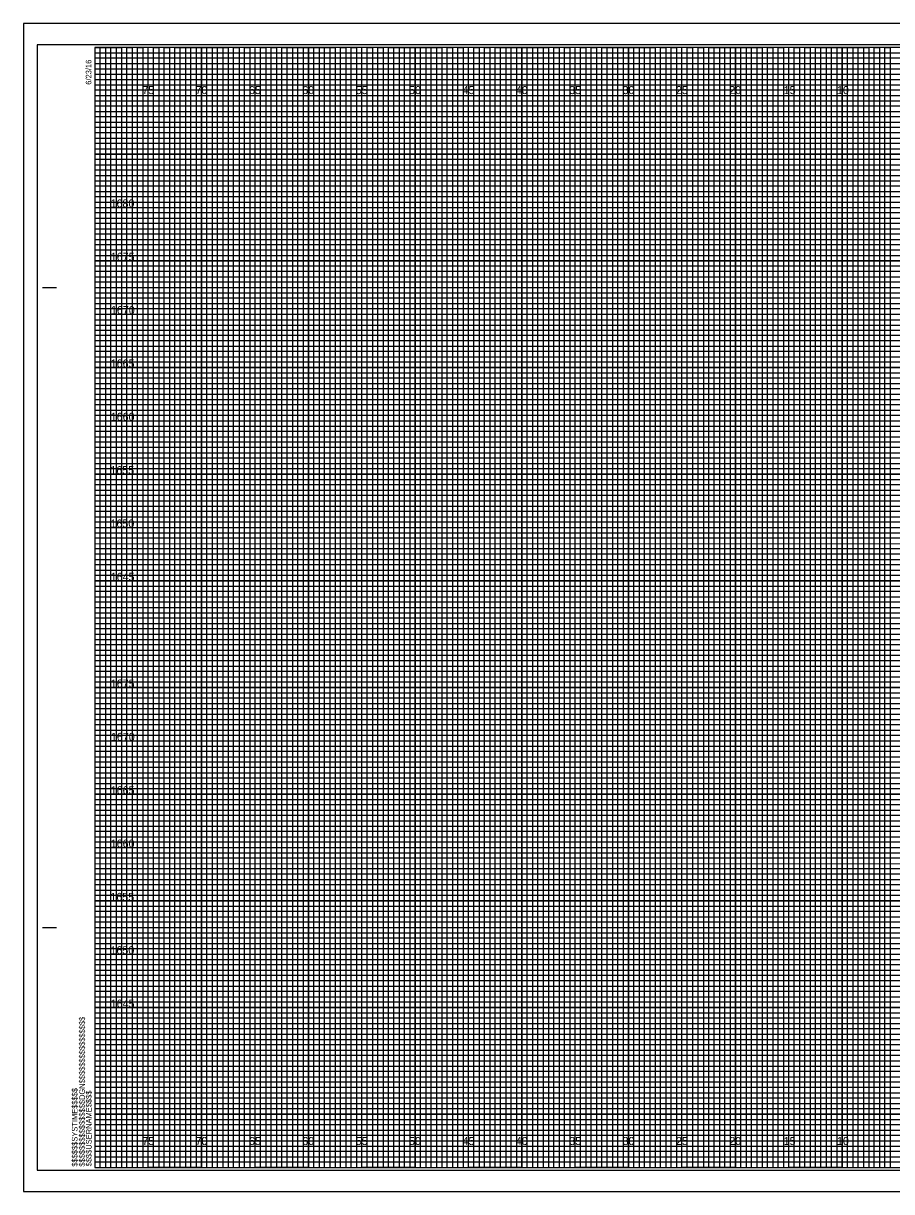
# Model space of a CAD drawing. Extents: x -7 to 162, y -2 to 217.
# Drawn here: x -6.7 to 74.6, y -2.3 to 107.3 of the extents above; entities that cross this region are included whole.
import ezdxf

# ---------------------------------------------------------------- set-up
doc = ezdxf.new("R2010")
doc.units = 0
for name, color, linetype in [('Prop XS Gore Control Minimum', 7, 'Continuous'), ('Raster_Level_0', 7, 'Continuous'), ('Scratch_Level_3', 7, 'Continuous'), ('Sheet Cross Section CELL', 7, 'Continuous'), ('Sheet Cross Section Grid Middle CELL', 7, 'Continuous'), ('Sheet Cross Section Grid Minor 1 CELL', 7, 'Continuous'), ('Sheet Cross Section Grid Minor 2 CELL', 7, 'Continuous'), ('Sheet Cutting Line CELL', 7, 'Continuous'), ('Sheet DOT Grid CELL', 7, 'Continuous'), ('Sheet Plot Border Inside CELL', 7, 'Continuous'), ('Sheet Plot Border Outside CELL', 7, 'Continuous')]:
    doc.layers.add(name, color=color, linetype=linetype)

msp = doc.modelspace()

# ---------------------------------------------------------------- linework, layer by layer
at = {"layer": 'Prop XS Gore Control Minimum'}
for p, q in [((5, 105), (0, 105)), ((5, 0), (5, 105)), ((15, 105), (10, 105)), ((10, 105), (10, 0)), ((15, 0), (15, 105)), ((25, 105), (20, 105)), ((20, 105), (20, 0)), ((25, 0), (25, 105)), ((35, 105), (30, 105)), ((30, 105), (30, 0)), ((35, 0), (35, 105)), ((45, 105), (40, 105)), ((40, 105), (40, 0)), ((45, 0), (45, 105)), ((55, 105), (50, 105)), ((50, 105), (50, 0)), ((55, 0), (55, 105)), ((65, 105), (60, 105)), ((60, 105), (60, 0)), ((65, 0), (65, 105)), ((75, 105), (70, 105)), ((70, 105), (70, 0)), ((10, 0), (5, 0)), ((20, 0), (15, 0)), ((30, 0), (25, 0)), ((40, 0), (35, 0)), ((50, 0), (45, 0)), ((60, 0), (55, 0)), ((70, 0), (65, 0))]:
    msp.add_line(p, q, dxfattribs=at)
for points in [[(0, 100), (160, 100), (160, 95), (0, 95)], [(0, 90), (160, 90), (160, 85), (0, 85)], [(0, 80), (160, 80), (160, 75), (0, 75)], [(0, 70), (160, 70), (160, 65), (0, 65)], [(0, 60), (160, 60), (160, 55), (0, 55)], [(0, 50), (160, 50), (160, 45), (0, 45)], [(0, 40), (160, 40), (160, 35), (0, 35)], [(0, 30), (160, 30), (160, 25), (0, 25)], [(0, 20), (160, 20), (160, 15), (0, 15)], [(0, 10), (160, 10), (160, 5), (0, 5)]]:
    msp.add_lwpolyline(points, dxfattribs=at)
at = {"layer": 'Sheet Cross Section CELL'}
for p, q in [((-4.9, 82.5), (-3.65, 82.5)), ((-4.85, 82.5), (-3.6, 82.5)), ((-4.9, 22.5), (-3.65, 22.5)), ((-4.85, 22.5), (-3.6, 22.5)), ((0, 0), (0, 0)), ((0, 0), (0, 0)), ((0, 0), (0, 0)), ((0, 0), (0, 0)), ((0, 0), (0, 0)), ((0, 0), (0, 0)), ((0, 0), (0, 0))]:
    msp.add_line(p, q, dxfattribs=at)
msp.add_lwpolyline([(160, 105), (0, 105), (0, 0), (160, 0)], close=True, dxfattribs=at)
at = {"layer": 'Sheet Cross Section Grid Middle CELL'}
for points in [[(0, 105), (2.5, 105), (2.5, 0), (7.5, 0), (7.5, 105), (12.5, 105), (12.5, 0), (17.5, 0), (17.5, 105), (22.5, 105), (22.5, 0), (27.5, 0), (27.5, 105), (32.5, 105), (32.5, 0), (37.5, 0), (37.5, 105), (42.5, 105), (42.5, 0), (47.5, 0), (47.5, 105), (52.5, 105), (52.5, 0), (57.5, 0), (57.5, 105), (62.5, 105), (62.5, 0), (67.5, 0), (67.5, 105), (72.5, 105), (72.5, 0), (77.5, 0)], [(0, 102.5), (137.5, 102.5)], [(0, 92.5), (160, 92.5), (160, 97.5), (0, 97.5)], [(0, 82.5), (160, 82.5), (160, 87.5), (0, 87.5)], [(0, 72.5), (160, 72.5), (160, 77.5), (0, 77.5)], [(0, 62.5), (160, 62.5), (160, 67.5), (0, 67.5)], [(0, 52.5), (160, 52.5), (160, 57.5), (0, 57.5)], [(0, 42.5), (160, 42.5), (160, 47.5), (0, 47.5)], [(0, 32.5), (160, 32.5), (160, 37.5), (0, 37.5)], [(0, 22.5), (160, 22.5), (160, 27.5), (0, 27.5)], [(0, 12.5), (160, 12.5), (160, 17.5), (0, 17.5)], [(0, 2.5), (160, 2.5), (160, 7.5), (0, 7.5)]]:
    msp.add_lwpolyline(points, dxfattribs=at)
at = {"layer": 'Sheet Cross Section Grid Minor 1 CELL'}
for p, q in [((0, 104.5), (130, 104.5)), ((130, 103.99), (0, 103.99)), ((0, 103.99), (0, 103.5)), ((0, 103.5), (130, 103.5)), ((130, 102.95), (0, 102.95)), ((0, 102.95), (0, 102)), ((0, 102), (160, 102))]:
    msp.add_line(p, q, dxfattribs=at)
for points in [[(0, 101.5), (135, 101.5), (160, 101.5), (160, 101), (0, 101)], [(0, 100.5), (160, 100.5), (160, 99.5), (0, 99.5)], [(0, 99), (160, 99), (160, 98.5), (0, 98.49)], [(0, 98), (160, 98), (160, 97), (0, 97)], [(0, 96.5), (160, 96.5), (160, 96), (0, 96)], [(0, 95.5), (160, 95.5), (160, 94.5), (0, 94.5)], [(0, 94), (160, 94), (160, 93.5), (0, 93.5)], [(0, 93), (160, 93), (160, 92), (0, 92)], [(0, 91.5), (160, 91.5), (160, 91), (0, 91)], [(0, 90.5), (160, 90.5), (160, 89.5), (0, 89.5)], [(0, 89), (160, 89), (160, 88.5), (0, 88.5)], [(0, 88), (160, 88), (160, 86.98), (160, 86.5), (160, 86), (0, 86)], [(0, 87), (160, 87), (160, 86.5), (0, 86.5)], [(0, 85.5), (160, 85.5), (160, 84.5), (0, 84.52)], [(0, 84.52), (160, 84.5), (160, 84), (0, 84)], [(0, 83.5), (160, 83.5), (160, 83), (0, 83)], [(0, 82), (160, 82), (160, 81.5), (0, 81.5)], [(0, 81), (160, 81), (160, 80.5), (0, 80.5)], [(-0.04, 79.45), (160, 79.45), (160, 78.94), (-0.04, 78.94)], [(0, 78.5), (160, 78.5), (160, 78), (0, 78)], [(0, 77), (160, 77), (160, 76.5), (0, 76.5)], [(0, 76), (160, 76), (160, 75.5), (0, 75.5)], [(0, 74.5), (160, 74.5), (160, 74), (0, 74)], [(0, 73.5), (160, 73.5), (160, 73), (0, 73)], [(0, 72), (160, 72), (160, 71.5), (0, 71.5)], [(0, 71), (160, 71), (160, 70.5), (0, 70.5)], [(0, 69.5), (160, 69.5), (160, 68.99), (0, 69)], [(0, 68.5), (160, 68.5), (160, 68), (0, 68)], [(0, 67), (160, 67), (160, 66.5), (0, 66.5)], [(0, 66), (160, 66), (160, 65.5), (0, 65.5)], [(0, 64.5), (160, 64.5), (160, 64), (0, 64)], [(0, 63.5), (160, 63.5), (160, 63), (0, 63)], [(0, 62), (160, 62), (160, 61.5), (0, 61.5)], [(0, 61), (160, 61), (160, 60.5), (0, 60.5)], [(0, 59.5), (160, 59.5), (160, 59), (0, 59)], [(0, 58.5), (160.03, 58.45), (160, 58), (0, 58)], [(0, 57), (160, 57), (160, 56.5), (0, 56.5)], [(0, 56), (160, 56), (160, 55.5), (0, 55.5)], [(0, 54.5), (160, 54.5), (160, 54), (0, 54)], [(0, 53.5), (160, 53.5), (160, 53), (0, 53)], [(0, 52), (160, 52), (160, 51.5), (0, 51.5)], [(0, 51), (160, 51), (160, 50.5), (0, 50.5)], [(0, 49.5), (160, 49.5), (160, 49), (0, 49)], [(0, 48.5), (160, 48.5), (160, 48), (0, 48)], [(0, 47), (160, 47), (160, 46.5), (0, 46.5)], [(0, 46), (160, 46), (160, 45.5), (0, 45.5)], [(0, 44.5), (160, 44.5), (160, 44), (0, 44)], [(0, 43.5), (160, 43.5), (160, 43), (0, 43)], [(0, 42), (160, 42), (160, 41.5), (0, 41.5)], [(0, 41), (160, 41), (160, 40.5), (0, 40.5)], [(0, 39.5), (160, 39.5), (160, 38.99), (0, 39)], [(0, 38.5), (160, 38.5), (160, 38), (0, 38)], [(0, 37), (160, 37), (160, 36.5), (0, 36.5)], [(0, 36), (160, 36), (160, 35.5), (0, 35.5)], [(0, 34.5), (160, 34.5), (160, 34), (0, 34)], [(0, 33.5), (160, 33.5), (160, 33), (0, 33)], [(0, 32), (160, 32), (160, 31.5), (0, 31.5)], [(0, 31), (160, 31), (160, 30.5), (0, 30.5)], [(0, 29.5), (160, 29.5), (160, 29), (0, 29)], [(0, 28.5), (160.03, 28.46), (160, 28), (0, 28)], [(0, 27), (160, 27), (160, 26.5), (0, 26.5)], [(0, 26), (160, 26), (160, 25.5), (0, 25.5)], [(0, 24.5), (160, 24.5), (160, 24), (0, 24)], [(0, 23.5), (160, 23.5), (160, 23), (0, 23)], [(0, 22), (160, 22), (160, 21.5), (0, 21.5)], [(0, 21), (160, 21), (160, 20.5), (0, 20.5)], [(0, 19.5), (160, 19.5), (160, 19), (0, 19)], [(0, 18.5), (160, 18.5), (160, 18), (0, 18)], [(0, 17), (160, 17), (160, 16.5), (0, 16.5)], [(0, 16), (160, 16), (160, 15.5), (0, 15.5)], [(0, 14.5), (160, 14.5), (160, 14), (0, 14)], [(0, 13.5), (160, 13.5), (160, 13), (0, 13)], [(0, 12), (160, 12), (160, 11.5), (0, 11.5)], [(0, 11), (160, 11), (160, 10.5), (0, 10.5)], [(0, 9.5), (160, 9.5), (160, 9), (0, 9)], [(0, 8.5), (160, 8.5), (160, 8), (0, 8)], [(0, 7), (160, 7), (160, 6.5), (0, 6.5)], [(0, 6), (160, 6), (160, 5.5), (0, 5.5)], [(0, 4.5), (160, 4.5), (160, 4), (0, 4)], [(0, 3.5), (160, 3.5), (160, 3), (0, 3)], [(0, 2), (160, 2), (160, 1.5), (0, 1.5)], [(0, 1), (160, 1), (160, 0.5), (0, 0.5)]]:
    msp.add_lwpolyline(points, dxfattribs=at)
at = {"layer": 'Sheet Cross Section Grid Minor 2 CELL'}
for points in [[(0, 0), (0.5, 0), (0.5, 105), (1, 105), (1, 0)], [(1, 0), (1.5, 0), (1.5, 105), (2, 105), (2, 0)], [(2.5, 0), (3, 0), (3, 105), (3.5, 105), (3.5, 0)], [(3.5, 0), (4, 0), (4, 105), (4.5, 105), (4.5, 0)], [(5, 0), (5.5, 0), (5.5, 105), (6, 105), (6, 0)], [(6, 0), (6.5, 0), (6.5, 105), (7, 105), (7, 0)], [(7.5, 0), (8, 0), (8, 105), (8.5, 105), (8.5, 0)], [(8.5, 0), (9, 0), (9, 105), (9.5, 105), (9.5, 0)], [(10, 0), (10.5, 0), (10.5, 105), (11, 105), (11, 0)], [(11, 0), (11.5, 0), (11.5, 105), (12, 105), (12, 0)], [(12.5, 0), (13, 0), (13, 105), (13.5, 105), (13.5, 0)], [(13.5, 0), (14, 0), (14, 105), (14.5, 105), (14.5, 0)], [(15, 0), (15.5, 0), (15.5, 105), (16, 105), (16, 0)], [(16, 0), (16.5, 0), (16.5, 105), (17, 105), (17, 0)], [(17.5, 0), (18, 0), (18, 105), (18.5, 105), (18.5, 0)], [(18.5, 0), (19, 0), (19, 105), (19.5, 105), (19.5, 0)], [(20, 0), (20.5, 0), (20.5, 105), (21, 105), (21, 0)], [(21, 0), (21.5, 0), (21.5, 105), (22, 105), (22, 0)], [(22.5, 0), (23, 0), (23, 105), (23.5, 105), (23.5, 0)], [(23.5, 0), (24, 0), (24, 105), (24.5, 105), (24.5, 0)], [(25, 0), (25.5, 0), (25.5, 105), (26, 105), (26, 0)], [(26, 0), (26.5, 0), (26.5, 105), (27, 105), (27, 0)], [(27.5, 0), (28, 0), (28, 105), (28.5, 105), (28.5, 0)], [(28.5, 0), (29, 0), (29, 105), (29.5, 105), (29.5, 0)], [(30, 0), (30.5, 0), (30.5, 105), (31, 105), (31, 0)], [(31, 0), (31.5, 0), (31.5, 105), (32, 105), (32, 0)], [(32.5, 0), (33, 0), (33, 105), (33.5, 105), (33.5, 0)], [(33.5, 0), (34, 0), (34, 105), (34.5, 105), (34.5, 0)], [(35, 0), (35.5, 0), (35.5, 105), (36, 105), (36, 0)], [(36, 0), (36.5, 0), (36.5, 105), (37, 105), (37, 0)], [(37.5, 0), (38, 0), (38, 105), (38.5, 105), (38.5, 0)], [(38.5, 0), (39, 0), (39, 105), (39.5, 105), (39.5, 0)], [(40, 0), (40.5, 0), (40.5, 105), (41, 105), (41, 0)], [(41, 0), (41.5, 0), (41.5, 105), (42, 105), (42, 0)], [(42.5, 0), (43, 0), (43, 105), (43.5, 105), (43.5, 0)], [(43.5, 0), (44, 0), (44, 105), (44.5, 105), (44.5, 0)], [(45, 0), (45.5, 0), (45.5, 105), (46, 105), (46, 0)], [(46, 0), (46.5, 0), (46.5, 105), (47, 105), (47, 0)], [(47.5, 0), (48, 0), (48, 105), (48.5, 105), (48.5, 0)], [(48.5, 0), (49, 0), (49, 105), (49.5, 105), (49.5, 0)], [(50, 0), (50.5, 0), (50.5, 105), (51, 105), (51, 0)], [(51, 0), (51.5, 0), (51.5, 105), (52, 105), (52, 0)], [(52.5, 0), (53, 0), (53, 105), (53.5, 105), (53.5, 0)], [(53.5, 0), (54, 0), (54, 105), (54.5, 105), (54.5, 0)], [(55, 0), (55.5, 0), (55.5, 105), (56, 105), (56, 0)], [(56, 0), (56.5, 0), (56.5, 105), (57, 105), (57, 0)], [(57.5, 0), (58, 0), (58, 105), (58.5, 105), (58.5, 0)], [(58.5, 0), (59, 0), (59, 105), (59.5, 105), (59.5, 0)], [(60, 0), (60.5, 0), (60.5, 105), (61, 105), (61, 0)], [(61, 0), (61.5, 0), (61.5, 105), (62, 105), (62, 0)], [(62.5, 0), (63, 0), (63, 105), (63.5, 105), (63.5, 0)], [(63.5, 0), (64, 0), (64, 105), (64.5, 105), (64.5, 0)], [(65, 0), (65.5, 0), (65.5, 105), (66, 105), (66, 0)], [(66, 0), (66.5, 0), (66.5, 105), (67, 105), (67, 0)], [(67.5, 0), (68, 0), (68, 105), (68.5, 105), (68.5, 0)], [(68.5, 0), (69, 0), (69, 105), (69.5, 105), (69.5, 0)], [(70, 0), (70.5, 0), (70.5, 105), (71, 105), (71, 0)], [(71, 0), (71.5, 0), (71.5, 105), (72, 105), (72, 0)], [(72.5, 0), (73, 0), (73, 105), (73.5, 105), (73.5, 0)], [(73.5, 0), (74, 0), (74, 105), (74.5, 105), (74.5, 0)]]:
    msp.add_lwpolyline(points, dxfattribs=at)
at = {"layer": 'Sheet Cutting Line CELL'}
for p, q in [((161.65, 107.25), (-6.7, 107.25)), ((-6.7, 107.25), (-6.7, -2.25)), ((-6.7, -2.25), (161.65, -2.25))]:
    msp.add_line(p, q, dxfattribs=at)
at = {"layer": 'Sheet DOT Grid CELL'}
for p, q in [((5, 0), (5, 105)), ((10, 0), (10, 105)), ((15, 0), (15, 105)), ((20, 0), (20, 105)), ((25, 0), (25, 105)), ((30, 0), (30, 105)), ((35, 0), (35, 105)), ((40, 0), (40, 105)), ((45, 0), (45, 105)), ((50, 0), (50, 105)), ((55, 0), (55, 105)), ((60, 0), (60, 105)), ((65, 0), (65, 105)), ((70, 0), (70, 105)), ((0, 100), (160, 100)), ((0, 95), (160, 95)), ((0, 90), (160, 90)), ((0, 85), (160, 85)), ((0, 80), (160, 80)), ((0, 75), (160, 75)), ((0, 70), (160, 70)), ((0, 65), (160, 65)), ((0, 60), (160, 60)), ((0, 55), (160, 55)), ((0, 50), (160, 50)), ((0, 45), (160, 45)), ((0, 40), (160, 40)), ((0, 35), (160, 35)), ((0, 30), (160, 30)), ((0, 25), (160, 25)), ((0, 20), (160, 20)), ((0, 15), (160, 15)), ((0, 10), (160, 10)), ((0, 5), (160, 5))]:
    msp.add_line(p, q, dxfattribs=at)
at = {"layer": 'Sheet Plot Border Inside CELL'}
msp.add_lwpolyline([(-5.4, -0.25), (161.2, -0.25), (161.2, 105.25), (-5.4, 105.25)], close=True, dxfattribs=at)
at = {"layer": 'Sheet Plot Border Outside CELL'}
msp.add_lwpolyline([(-6.7, -2.25), (161.65, -2.25), (161.65, 107.25), (-6.7, 107.25)], close=True, dxfattribs=at)

# ---------------------------------------------------------------- texts
at = {"layer": 'Raster_Level_0'}
for s, p in [('75', (4.44, 100.62)), ('70', (9.43, 100.62)), ('65', (14.44, 100.62)), ('60', (19.43, 100.62)), ('55', (24.44, 100.62)), ('50', (29.43, 100.62)), ('45', (34.44, 100.62)), ('40', (39.43, 100.62)), ('35', (44.44, 100.62)), ('30', (49.43, 100.62)), ('25', (54.44, 100.62)), ('20', (59.43, 100.62)), ('15', (64.53, 100.62)), ('10', (69.52, 100.62)), ('75', (4.44, 2.12)), ('70', (9.43, 2.12)), ('65', (14.44, 2.12)), ('60', (19.43, 2.12)), ('55', (24.44, 2.12)), ('50', (29.43, 2.12)), ('45', (34.44, 2.12)), ('40', (39.43, 2.12)), ('35', (44.44, 2.12)), ('30', (49.43, 2.12)), ('25', (54.44, 2.12)), ('20', (59.43, 2.12)), ('15', (64.53, 2.12)), ('10', (69.52, 2.12))]:
    msp.add_text(s, height=0.75, dxfattribs=at).set_placement(p)
at = {"layer": 'Scratch_Level_3'}
for s, p in [('1680', (1.47, 90)), ('1675', (1.49, 85)), ('1670', (1.5, 80)), ('1665', (1.48, 75)), ('1660', (1.48, 70)), ('1655', (1.45, 65)), ('1650', (1.46, 60)), ('1645', (1.48, 55)), ('1675', (1.49, 45)), ('1670', (1.5, 40)), ('1665', (1.48, 35)), ('1660', (1.48, 30)), ('1655', (1.45, 25)), ('1650', (1.46, 20)), ('1645', (1.48, 15))]:
    msp.add_text(s, height=0.75, dxfattribs=at).set_placement(p)
at = {"layer": 'Sheet Cross Section CELL'}
for s, p in [('6/23/16', (-0.33, 101.5)), ('$$$$$$$$$$$$$$$$DGN$$$$$$$$$$$$$$$$', (-0.94, 0.09)), ('$$$$$$SYSTIME$$$$$', (-1.63, 0.09)), ('$$$$USERNAME$$$$', (-0.31, 0.12))]:
    msp.add_text(s, height=0.525, rotation=90, dxfattribs=at).set_placement(p)

doc.saveas('drawing.dxf')
